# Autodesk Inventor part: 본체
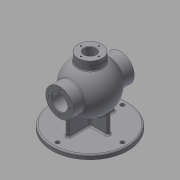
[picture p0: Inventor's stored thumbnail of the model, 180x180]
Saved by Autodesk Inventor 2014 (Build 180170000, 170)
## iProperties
Created: 2020-08
Part Number: 본체
Material: Generic
Document SubType Name: Modeling
Designer: kh
Density: 1 g/cm^3
Appearance: Default
Author: kh
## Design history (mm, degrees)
sketch "Sketch1"
  geometry: L1 (0, 53)-(0, -53); A1 r 53 centre (0, 0) between (0, -53) and (0, 53); A2 r 43 centre (0, 0) between (0, -43) and (0, 43); 1 further point
  constraints: 4 point on circle, 2 centre point, 2 coincident, 2 end point, 2 point on line, 1 midpoint, 1 vertical
  dimensions: "d1" = 53 radius of A1; "d4" = 43 radius of A2
revolve "Revolution1" stored, may be unused: angle "d2" = 90 deg
revolve "Revolution2" stored, may be unused: angle "d5" = 90 deg
workplane "Work Plane1"
sketch "Sketch2"
  geometry: C1 r 31 at (0, 0); 1 further point
  constraints: 1 centre point, 1 coincident
  dimensions: "d7" = 62 diameter of C1
extrude "Extrusion1" join sketch "Sketch2" stored distance "d8" = 10; taper "d9" = 0 deg
sketch "Sketch3"
  geometry: C1 r 17.5 at (0, 0); 1 further point
  constraints: 1 centre point, 1 coincident
  dimensions: "d10" = 35 diameter of C1
extrude "Extrusion2" cut sketch "Sketch3" stored distance "d11" = 10; taper "d12" = 0 deg
mirror "Mirror1"
workplane "Work Plane2"
sketch "Sketch4"
  geometry: C1 r 85 at (0, 0); 1 further point
  constraints: 1 centre point, 1 coincident
  dimensions: "d14" = 170 diameter of C1
extrude "Extrusion3" join sketch "Sketch4" distance "d15" = 10; taper "d16" = 0 deg
workplane "Work Plane4"
  workplane "Work Plane3"
sketch "Sketch5"
  geometry: C1 r 18.5 at (0, 0); 1 further point
  constraints: 1 centre point, 1 coincident
  dimensions: "d19" = 37 diameter of C1
extrude "Extrusion4" cut sketch "Sketch5" distance "d20" = 1.75; taper "d21" = 0 deg
workplane "Work Plane5"
sketch "Sketch6"
  geometry: C1 r 27 at (0, 0); 1 further point
  constraints: 1 centre point, 1 coincident
  dimensions: "d23" = 54 diameter of C1
extrude "Extrusion5" join sketch "Sketch6" stored distance "d24" = 1.75; taper "d25" = 0 deg
sketch "Sketch7"
  geometry: C1 r 13 at (0, 0); 1 further point
  constraints: 1 centre point, 1 coincident
  dimensions: "d26" = 26 diameter of C1
extrude "Extrusion6" cut sketch "Sketch7" stored distance "d27" = 1.75; taper "d28" = 0 deg
sketch "Sketch8"
  geometry: A1 r 20 centre (0, 0) between (0, 20) and (0, -20); 3 further points
  constraints: 4 point on circle, 2 horizontal alignment, 2 vertical alignment, 1 centre point, 1 coincident
  dimensions: "d29" = 40 diameter of A1
hole "Hole1" sketch "Sketch8" at (0, 20), (0, -20), (-20, 0), (20, 0) diameter "d30" = 3.242; stored, may be unused: countersink angle "d34" = 90 deg, drill point angle "d36" = 118 deg; dims "d31" = 12, "d32" = 4, "d33" = 2, "d35" = 15
sketch "Sketch9"
  geometry: A1 r 24 centre (0, 0) between (0, 24) and (24, 0); 3 further points
  constraints: 4 point on circle, 2 horizontal alignment, 2 vertical alignment, 1 centre point, 1 coincident
  dimensions: "d37" = 48 diameter of A1
hole "Hole2" sketch "Sketch9" at (0, 24), (24, 0), (-24, 0), (0, -24) diameter "d38" = 3.242; stored, may be unused: countersink angle "d42" = 90 deg, drill point angle "d44" = 118 deg; dims "d39" = 12, "d40" = 4, "d41" = 2, "d43" = 15
mirror "Mirror2"
sketch "Sketch10"
  geometry: L1 (-52, -4)-(52, -4); L2 (52, -4)-(52, 4); L3 (52, 4)-(-52, 4); L4 (-52, 4)-(-52, -4); L5 (-52, -4)-(52, 4); L6 (52, -4)-(-52, 4); L7 (-4, -43)-(4, -43); L8 (4, -43)-(4, 43); L9 (4, 43)-(-4, 43); L10 (-4, 43)-(-4, -43); L11 (-4, -43)-(4, 43); L12 (4, -43)-(-4, 43); 1 further point
  constraints: 24 end point, 4 midpoint, 4 parallel, 2 horizontal, 2 perpendicular
  dimensions: "d45" = 86 distance of L7.end L8.end; "d46" = 104 distance of L1.start L1.end; "d47" = 8 distance of L1.end L2.end; "d48" = 8 distance of L7.start L7.end
extrude "Extrusion7" join sketch "Sketch10" stored distance "d49" = 1.75; taper "d50" = 0 deg
fillet "Fillet1" dims "d51" = 3
fillet "Fillet2" dims "d52" = 3
fillet "Fillet3" dims "d53" = 3
chamfer "Chamfer1" distance "d54" = 1; stored, may be unused: second distance "d55" = 2, angle "d56" = 45 deg
sketch "Sketch11"
  geometry: C1 r 4.5 at (72.5, 0); C2 r 4.5 at (0, -72.5); C3 r 4.5 at (-72.5, 0); C4 r 4.5 at (0, 72.5); A1 r 72.5 centre (0, 0) between (72.5, 0) and (0, -72.5); 1 further point
  constraints: 5 centre point, 4 point on circle, 2 horizontal alignment, 2 vertical alignment, 1 coincident
  dimensions: "d57" = 145 diameter of A1; "d58" = 9 diameter of C1; "d59" = 9 diameter of C2; "d60" = 9 diameter of C3; "d61" = 9 diameter of C4
extrude "Extrusion8" cut sketch "Sketch11" stored distance "d62" = 0; taper "d63" = 0 deg
fillet "Fillet4" dims "d64" = 3
workplane "Work Plane6"
sketch "Sketch12"
  geometry: L1 (-27, 0)-(27, 0) reference; L2 (-27, -17.714)-(27, -17.714) reference; L3 (-22.825, -5.696)-(22.825, -5.696); L4 (22.825, -5.696)-(22.825, -12.304); L5 (22.825, -12.304)-(-22.825, -12.304); L6 (-22.825, -12.304)-(-22.825, -5.696); L7 (-22.825, -5.696)-(22.825, -12.304); L8 (-27, 0)-(-27, -17.714) reference; 2 further points
  constraints: 2 end point, 1 midpoint, 2 other
  dimensions: "d65" = 9 distance from line of L1 point (0, -9); "d66" = 27 distance from line of point (0, -9) L8
emboss "Emboss1" sketch "Sketch12" dims "d1" = 53, "d4" = 43, "d67" = 0.5, "d68" = 0
body "Solid1"
node "Projected Loop1"
other parameters: "d6" = 68, "d13" = -85, "d17" = -68, "d18" = 16
